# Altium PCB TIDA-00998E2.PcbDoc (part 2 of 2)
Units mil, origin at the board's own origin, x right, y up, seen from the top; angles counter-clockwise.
Board outline 2559.06 x 2559.06 mil, 2 copper layers (Top Layer, Bottom Layer), stack 62 mil thick; 110 components, 76 nets, 294 pads, 121 vias.
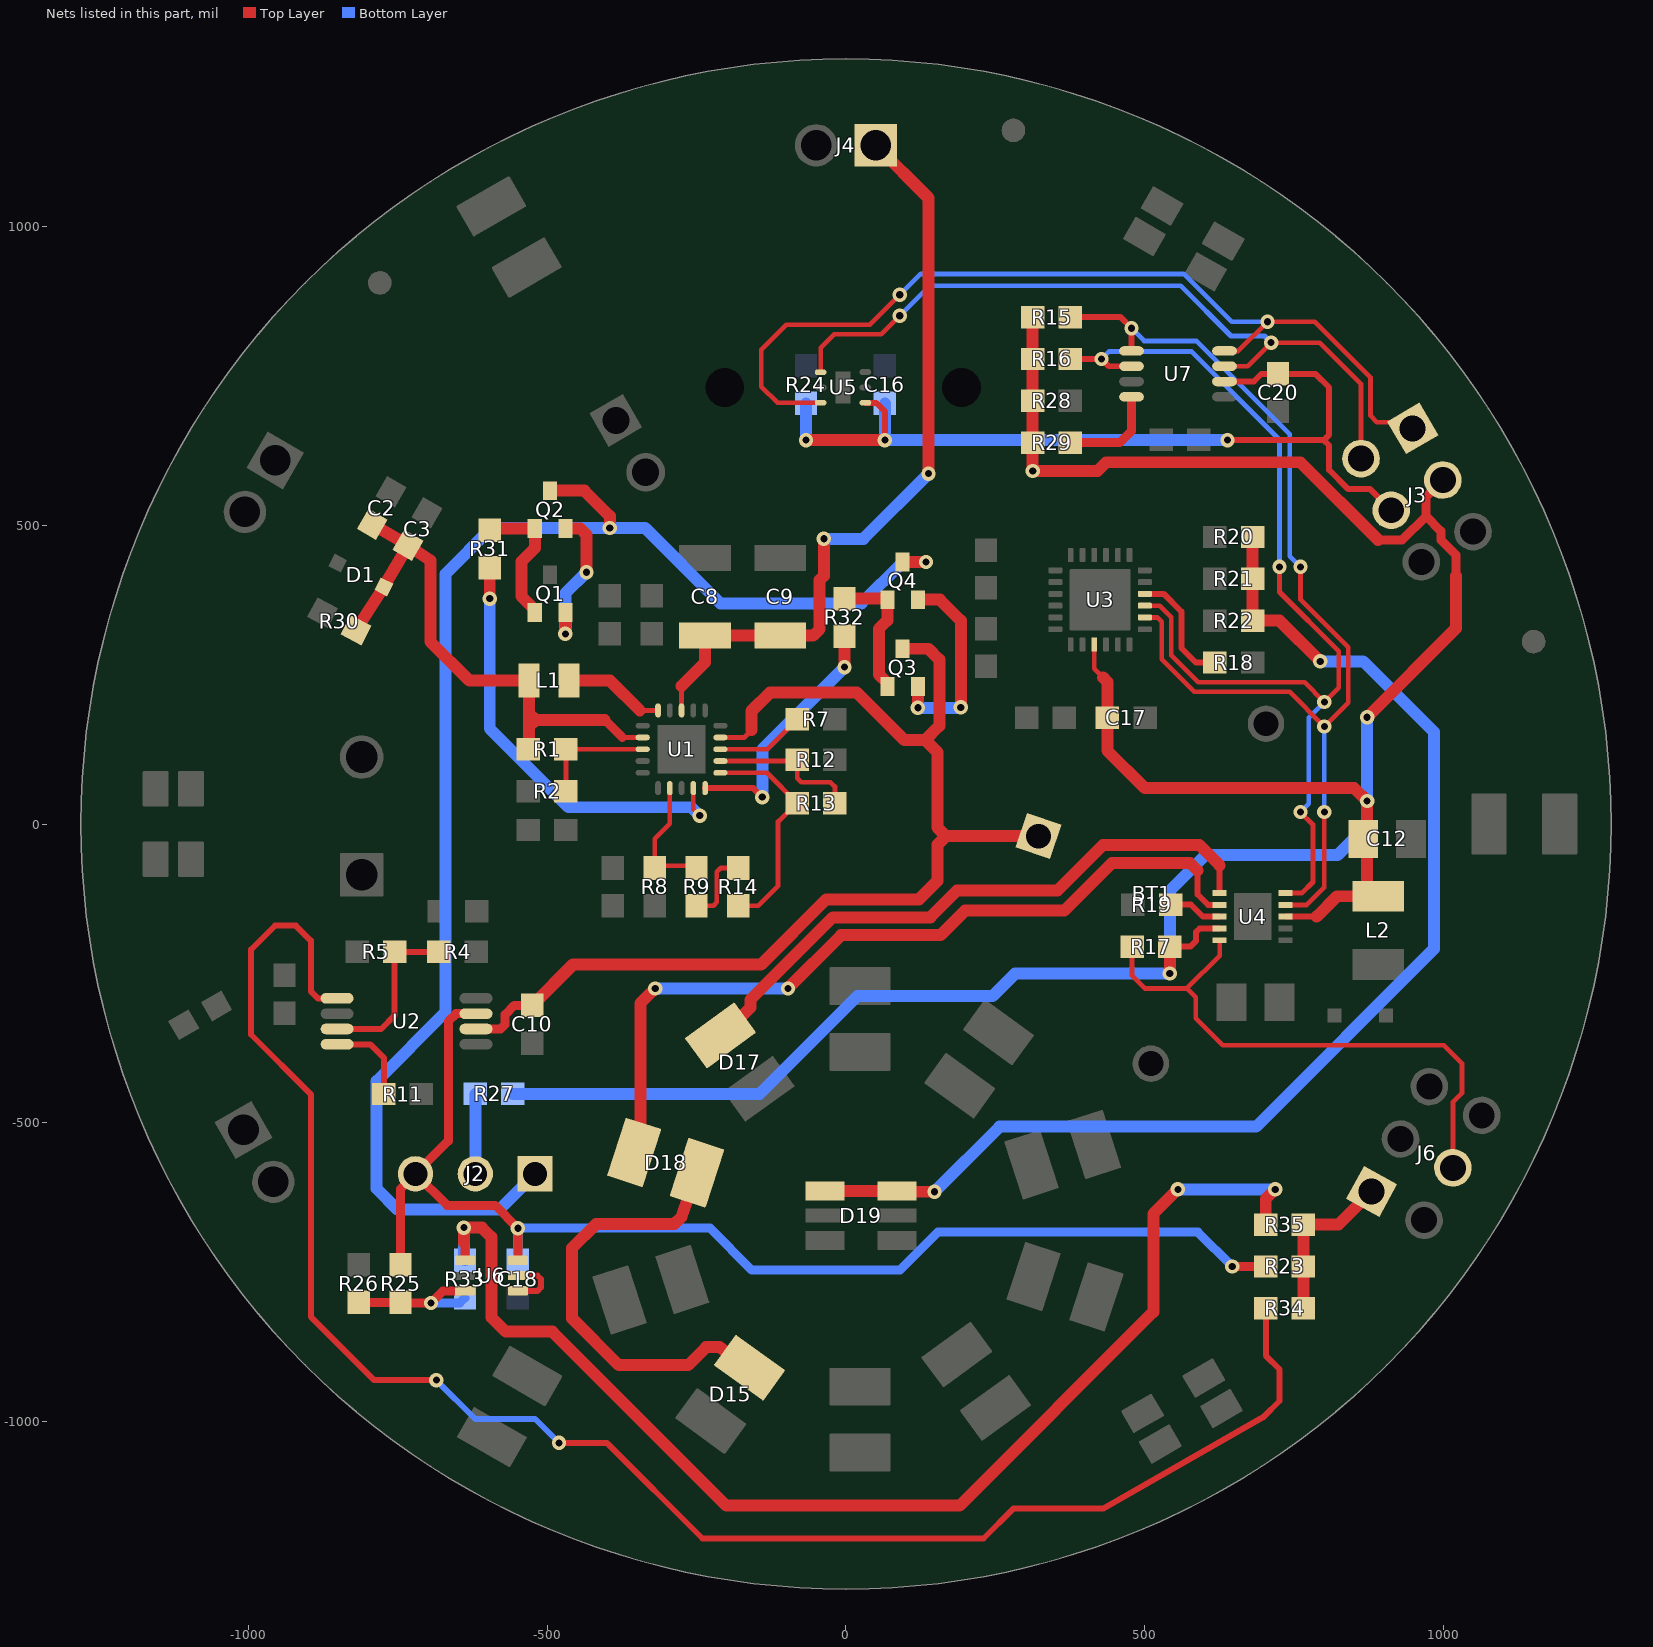
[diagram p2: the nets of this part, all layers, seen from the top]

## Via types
v1: diameter 24, hole 12, Top Layer to Bottom Layer, tented both sides, 107 vias
v2: diameter 19.68, hole 7.87, Top Layer to Bottom Layer, 10 vias
v3: diameter 19.68, hole 7.87, Top Layer to Bottom Layer, tented top, 4 vias

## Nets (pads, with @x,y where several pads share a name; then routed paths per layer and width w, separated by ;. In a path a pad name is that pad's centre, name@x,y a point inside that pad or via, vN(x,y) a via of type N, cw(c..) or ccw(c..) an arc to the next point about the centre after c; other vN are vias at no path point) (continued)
NetD15_2: D15.2 D18.1 | length 752.8
  Top Layer w20: D18.1@-249.35,-583.25 -275,-657 -287,-669 -418,-669 -458,-709 -458,-827 -380,-905 -264,-905 -234,-875 -211.29,-875 -207.87,-877.35 D15.2@-161.43,-909.33 D15.2@-161.26,-909.45
NetD17_2: D17.2 U4.1 | length 1037.2
  Top Layer w10: U4.1@624.88,-115.63 624.88,-69.12
  Top Layer w20: D17.2@-214.71,-347.22 -200.22,-347.22 -160,-307 -160,-294 -22,-156 141,-156 186,-111 354,-111 430,-35 590.76,-35 624.88,-69.12
NetD18_2: D18.2 U4.2 | length 1372.9
  Top Layer w10: 588,-78 588,-118 605.32,-135.32 U4.2@624.88,-135.32
  Top Layer w20: D18.2@-361.68,-546.75 -344,-529.07 -344,-300 v1(-319,-275) ; v1(-97,-275) -8,-186 158,-186 199,-145 365,-145 445,-65 575,-65 588,-78
  Bottom Layer w20: v1(-319,-275) v1(-97,-275)
NetD19_3: D19.3 D19.4 R20.2 R21.2 R22.2 | length 2069.8
  Top Layer w20: D19.3@-35.04,-613.66 D19.4@85.04,-613.66 86.38,-615 v1(148,-615) ; R20.2@680,480 R21.2@680,410 R22.2@680,340 725,340 v1(793,272)
  Bottom Layer w20: v1(148,-615) 257,-506 686,-506 983,-209 983,154 865,272 v1(793,272)
NetJ2_2: J2.2 R27.2 | length 133.7
  Bottom Layer w20: J2.2@-620,-585 R27.2@-620,-451.31
NetJ6_1: J6.1 R23.1 R34.2 R35.2 | length 278.7
  Top Layer w20: R34.2@765,-810 R35.2@765,-670 823.51,-670 J6.1@879.16,-614.35 J6.1@879.16,-615.84
NetL1_2: L1.2 U1.20 | length 169.7
  Top Layer w8: -344.96,189.96 U1.20@-314.37,189.96
  Top Layer w20: L1.2@-463.33,240 -395,240 -344.96,189.96
NetQ1_1: Q1.1 Q2.1 R31.2 | length 235.7
  Top Layer w20: R31.2@-595.78,491.5 -592.84,494.43 Q2.1@-520.47,494.43 -520.47,461.27 -542.88,438.86 -542.88,380.97 -520.47,358.56 Q1.1@-520.47,353.78
NetQ1_2: Q1.2 Q2.2 | length 256
  Top Layer w20: v1(-469.29,318) Q1.2@-469.29,353.78 ; Q2.2@-469.29,494.43 -444.43,494.43 -433.99,483.99 v1(-433.99,421)
  Bottom Layer w20: v1(-469.29,318) -469.29,385.7 v1(-433.99,421)
NetQ3_1: Q3.1 Q4.1 R32.2 | length 229.1
  Top Layer w20: R32.2@-2.59,376.91 67.27,376.91 Q4.1@69.09,375.08 69.09,340.57 55,326.48 55,250 69.09,235.91 Q3.1@69.09,230.08
NetQ3_2: Q3.2 Q4.2 | length 339
  Top Layer w20: v1(120.28,194.3) Q3.2@120.28,230.08 ; Q4.2@120.28,375.08 156.92,375.08 192,340 v1(192,195)
  Bottom Layer w20: v1(120.28,194.3) 191.3,194.3 v1(192,195)
NetR1_2: R1.2 R2.1 U1.3 | length 198.5
  Top Layer w8: R2.1@-468.5,55 R1.2@-468.5,125 U1.3@-339.96,125
NetR4_1: R4.1 R5.2 U2.3 | length 285.7
  Top Layer w10: U2.3@-851.14,-342.8 -777.5,-342.8 -754.7,-320 R5.2@-754.7,-213.74 R4.1@-681.2,-213.74
NetR7_2: R7.2 U1.13 | length 149.3
  Top Layer w8: U1.13@-210.04,125 -131.5,125 R7.2@-81.5,175
NetR8_2: R8.2 R9.1 U1.7 | length 215.6
  Top Layer w8: R8.2@-320,-73.58 R8.2@-320,-70 ; U1.7@-294.69,60.04 -294.69,0.31 -320,-25 R8.2@-320,-70 ; R9.1@-250,-73.58 -253.58,-70 R8.2@-320,-70
NetR9_2: R9.2 R14.2 | length 126
  Top Layer w8: R9.2@-250,-136.57 -221.57,-136.57 -216,-131 -216,-80 -209.58,-73.58 R14.2@-180,-73.58
NetR11_2: R11.2 U2.4 | length 148
  Top Layer w10: U2.4@-851.14,-368.39 -795.67,-368.39 -772.99,-391.06 R11.2@-772.99,-451.56
NetR12_2: R12.2 R13.1 U1.12 | length 256.4
  Top Layer w8: U1.12@-210.04,105.32 -83.42,105.32 R12.2@-81.5,107.24 -81.5,76.5 -75,70 -26,70 -18.5,62.5 R13.1@-18.5,35
NetR13_2: R13.2 R14.1 U1.11 | length 382.2
  Top Layer w8: U1.11@-210.04,85.63 -132.13,85.63 R13.2@-81.5,35 -82.72,35 -113.66,4.05 -113.66,-103.66 -146.57,-136.57 R14.1@-180,-136.57
NetR18_2: R18.2 U3.10 | length 200.5
  Top Layer w10: U3.10@499.8,384.84 531.16,384.84 561,355 561,294 585,270 R18.2@617.01,270
NetR19_2: R19.2 U4.3 | length 90.4
  Top Layer w10: R19.2@542.76,-135 577,-135 597,-155 U4.3@624.88,-155
NetR25_1: R25.1 R26.2 R33.1 U6.3 | length 247.4
  Top Layer w15: R26.2@-815,-801.5 -813.5,-800 R25.1@-745,-800 -744,-801 v1(-694,-801) -673.69,-780.69 U6.3@-637.27,-780.69
  Bottom Layer w15: v1(-694,-801) -645.77,-801 R33.1@-637.27,-792.5
NetR29_1: R29.1 U7.8 | length 167.3
  Top Layer w15: R29.1@375.26,637.75 457.75,637.75 477.5,657.5 U7.8@477.5,714.37
NetU6_4: U6.4 U6.5 | length 96.2
  Top Layer w10: U6.4@-548.68,-780.69 -515.69,-780.69 -510,-775 -510,-761 -515.91,-755.09 U6.5@-548.68,-755.09
RESET_LM: J6.4 R17.1 U4.5 | length 965.8
  Top Layer w8: R17.1@478.5,-205 478.5,-253.5 500,-275 570,-275 ; U4.5@624.88,-194.37 624.88,-220.12 570,-275 ; J6.4@1015,-575 1015,-465 1030,-450 1030,-400 1000,-370 630,-370 585,-325 585,-290 570,-275
SCL: R16.1 U3.9 U4.10 U7.6 | length 1745.3
  Top Layer w8: U3.9@499.8,365.16 524.84,365.16 544,346 544,282 589,237 767,237 v1(800,204) 824,228 824,289 725,388 v1(725,430) ; U4.10@735.12,-115.63 762.37,-115.63 781,-97 781,-1 v1(760,20)
  Top Layer w10: R16.1@375.26,777.75 v1(427.25,777.75) 439.45,765.55 U7.6@477.5,765.55
  Bottom Layer w8: v1(427.25,777.75) 439.49,790 578,790 725,643 v1(725,430) ; v1(760,20) 774,34 774,178 v1(800,204)
SCL1: J3.2 U5.4 U7.3 | length 1274.6
  Top Layer w8: U5.4@-42.4,755.59 -42.4,796.6 -20,819 59,819 v1(90,850) ; U7.3@633.02,765.55 671.55,765.55 v1(711,805) 792,805 861.37,735.63 J3.2@861.37,611.1
  Bottom Layer w8: v1(90,850) 140,900 560,900 643.87,816.13 699.87,816.13 v1(711,805)
SDA: R15.1 U3.8 U4.9 U7.5 | length 1790.6
  Top Layer w8: U3.8@499.8,345.47 520.53,345.47 528,338 528,275.37 582.37,221 742,221 v1(800,163) 840,203 840,295.63 760,375.63 v1(760,430) ; U4.9@735.12,-135.32 770.68,-135.32 800,-106 v1(800,20)
  Top Layer w10: R15.1@375.26,847.75 459.25,847.75 477.5,829.5 v1(477.5,829) U7.5@477.5,791.14
  Bottom Layer w8: v1(477.5,829) 498.5,808 586,808 742,652 742,448 v1(760,430) ; v1(800,20) v1(800,163)
SDA1: J3.1 U5.6 U7.4 | length 1550.7
  Top Layer w8: U5.6@-42.4,704.41 -114.41,704.41 -141.56,731.56 -141.56,793.44 -100,835 40,835 v1(90,885) ; U7.4@633.02,791.14 656.14,791.14 v1(705,840) 784,840 877.37,746.63 877.37,682.63 888,672 937.26,672 J3.1@947.7,661.56
  Bottom Layer w8: v1(90,885) 125,920 565,920 645,840 v1(705,840)
STAT_PMUX: R34.1 U2.1 | length 2926.7
  Top Layer w10: U2.1@-851.14,-291.61 -883.39,-291.61 -895,-280 -895,-195 -920,-170 -955,-170 -995,-210 -995,-352 -895,-452 -895,-824 -789,-930 v1(-685,-930) ; v1(-480,-1035) -400,-1035 -240,-1195 230,-1195 280,-1145 430,-1145 698.63,-991.36 725,-964.99 725,-912 702.01,-889.01 R34.1@702.01,-810
  Bottom Layer w10: v1(-685,-930) -620,-995 -520,-995 v1(-480,-1035)
VBAT_PRI: BT1.1 C10.1 Q3.3 U1.14 U2.6 | length 1933
  Top Layer w8: U1.14@-210.04,144.69 -170.31,144.69 -158,157
  Top Layer w15: U2.6@-618.86,-342.8 -577.8,-342.8 -570,-335 -570,-318.8 -554.7,-303.5 C10.1@-525,-303.5
  Top Layer w20: C10.1@-525,-303.5 -456.5,-235 -142,-235 -33,-126 122,-126 153,-95 153,-34.64 167.32,-20.32 ; -158,157 -158,189 -127,220 18,220 97.5,140.5 132.5,140.5 ; Q3.3@94.68,293.07 137.93,293.07 156,275 156,164 132.5,140.5 ; BT1.1@322.04,-20.32 167.32,-20.32 ; 132.5,140.5 153,120 153,-6 167.32,-20.32
VBAT_SEC: C8.1 C9.1 J4.1 U1.18 | length 1295.9
  Top Layer w8: U1.18@-275,189.96 -275,231
  Top Layer w20: -275,231 -235.63,270.37 -235.63,313.07 -233.66,315.04 C9.1@-110,315.04 -54.96,315.04 -44,326 -44,408 -37,415 v1(-37,477) ; J4.1@50,1135 138,1047 v1(138,586)
  Bottom Layer w20: v1(-37,477) 29,477 v1(138,586)
VGS_PRI: R32.1 U1.10 | length 427.7
  Top Layer w10: U1.10@-235.63,60.04 -155.04,60.04 v1(-140,45)
  Top Layer w20: v1(-2.59,262.32) R32.1@-2.59,313.91
  Bottom Layer w20: v1(-140,45) -140,124.91 v1(-2.59,262.32)
VGS_SEC: R31.1 U1.9 | length 731
  Top Layer w8: U1.9@-255.32,60.04 -255.32,24.83 v1(-244.49,14)
  Top Layer w20: v1(-595.78,376.91) R31.1@-595.78,428.5
  Bottom Layer w20: v1(-595.78,376.91) -595.78,159.58 -464.2,28 -258.49,28 v1(-244.49,14)
VIN_BQ: C2.1 C3.1 D1.1 L1.1 R1.1 R30.2 U1.2 | length 946.2
  Top Layer w8: -374.17,144.69 U1.2@-339.96,144.69
  Top Layer w15: -403.49,174 -374.17,144.69
  Top Layer w20: R30.2@-819.4,324.34 D1.1@-772.9,396.6 C3.1@-732.3,466.04 ; C2.1@-792.3,501.04 C3.1@-732.3,466.04 ; R1.1@-531.5,125 -530.25,126.24 -530.25,163 ; -403.49,174 -519.25,174 ; C3.1@-732.3,466.04 -695,440.34 -695,305 -630,240 L1.1@-530.25,240 -530.25,185 ; -530.25,163 -519.25,174 ; -530.25,163 -530.25,185 ; -530.25,185 -519.25,174
VIN_DRIVER: C12.2 C17.1 J3.3 L2.1 R15.2 R16.2 R17.2 R27.1 R28.2 R29.2 U3.3 U4.4 U4.8 | length 4500.4
  Top Layer w8: U3.3@415.16,300.2 415.16,259.84 430,245
  Top Layer w10: R17.2@541.5,-205 576,-205 585,-196 585,-181 591.31,-174.69 U4.4@624.88,-174.69 ; U4.8@735.12,-155 787,-155
  Top Layer w15: 890,475 930,475 970,515 ; J3.3@998.16,575.23 970,547.07 970,515 ; 1020,415 1020,450 995,475 995,490 970,515
  Top Layer w20: R15.2@312.27,847.75 R16.2@312.27,777.75 R28.2@312.27,707.75 R29.2@312.27,637.75 v1(312.27,590.25) 420.25,590.25 435,605 760,605 890,475 ; 430,245 437.18,237.82 C17.1@437.18,177.73 437.18,122.82 500,60 850,60 v1(871.54,38.46) 871.54,-102.36 L2.1@890,-120.83 821.17,-120.83 787,-155 ; v1(541.5,-250) R17.2@541.5,-205 ; v1(871.54,178.46) 1020,326.93 1020,415
  Bottom Layer w20: R27.1@-557.01,-451.31 -144.31,-451.31 19,-288 245,-288 283,-250 v1(541.5,-250) 541.5,-111.5 600.99,-52 822,-52 871.54,-2.46 v1(871.54,38.46) v1(871.54,178.46)
VOUT_BQ: J2.1 Q2.3 Q4.3 | length 2472.9
  Top Layer w20: Q2.3@-494.88,557.43 -437.43,557.43 -395,515 v1(-395,495) ; Q4.3@94.68,438.07 v1(133.7,438.07)
  Bottom Layer w20: J2.1@-520,-585 -580,-645 -750,-645 -785,-610 -785,-430 -670,-315 -670,418 -593,495 v1(-395,495) -336,495 -210,369 25.61,369 94.68,438.07 v1(133.7,438.07)
VOUT_PMUX: C18.1 J2.3 R23.2 R25.2 U2.7 U6.6 | length 2137.5
  Top Layer w15: R25.2@-745,-737.01 -745,-610 J2.3@-720,-585 ; U2.7@-618.86,-317.2 -652.2,-317.2 -665,-330 -665,-530 J2.3@-720,-585 ; U6.6@-548.68,-729.5 v1(-548.68,-676) -586.68,-638 -667,-638 J2.3@-720,-585 ; v1(646,-740) R23.2@702.01,-740
  Bottom Layer w15: C18.1@-548.68,-729.5 v1(-548.68,-676) -227.37,-676 -157.37,-746 90,-746 153.63,-682.37 588.37,-682.37 v1(646,-740)
VPMUX_LOW: R33.2 R35.1 U6.1 | length 2128.6
  Top Layer w15: U6.1@-646.5,-729.5 U6.1@-637.27,-729.5 -637.27,-702.73 -639,-701
  Top Layer w20: -639,-701 v1(-639,-675) -609,-675 -593,-691 -593,-825 -569,-849 -491,-849 -200,-1140 190,-1140 514,-816 514,-652 v1(555,-611) ; R35.1@702.01,-670 702.01,-626.99 v1(718,-611)
  Bottom Layer w20: v1(-639,-675) -639,-727.77 R33.2@-637.27,-729.5 ; v1(555,-611) v1(718,-611)
VREF1: C16.1 C20.1 J3.4 R24.2 U5.1 U7.2 | length 1542.6
  Top Layer w10: U5.1@32.4,704.41 50.59,704.41 65,690 v1(65,642) ; U7.2@633.02,739.96 681.96,739.96 694.95,752.95 C20.1@722.5,752.95 785.05,752.95 808,730 808,651 799,642 ; v1(638,642) 799,642 ; J3.4@911.84,524.77 876.6,560 840,560 808,592 808,633 799,642
  Top Layer w20: v1(-67,642) v1(65,642)
  Bottom Layer w20: v1(-67,642) R24.2@-67,703.5 ; C16.1@65,703.5 v1(65,642) v1(638,642)
pads on no net: D19.1 D19.5 D19.6 FID1.1 FID2.1 FID3.1 FID4.1 FID5.1 FID6.1 U1.8 U3.7

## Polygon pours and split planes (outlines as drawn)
NetD1_2 on Top Layer "NETD1_2_L01_P002" (solid, remove dead copper, pour order 2): -1045,424.21 -1045,331.48 -1038.52,325 -871.48,325 -845,375 -845,415 -830,445 -860,460 -955,460 -965,470 -965,535 -990,560 -1023.27,560 -1045,538.27
GND on Bottom Layer "GND_L02_P004" (solid, remove dead copper, pour order 4): 15,1250 -70,1250 -220,1235 -450,1170 -685,1050 -845,925 -1015,735 -1125,550 -1185,410 -1230,245 -1250,45 -1250,-90 -1235,-220 -1200,-360 -1155,-485 -1080,-635 -985,-775 -895,-880 -750,-1005 -580,-1110 -410,-1185 -245,-1230 -95,-1250 35,-1250 185,-1240 345,-1205 565,-1120 800,-965 940,-825 1090,-620 1190,-390 1240,-185 1250,-10 1245,150 1210,320 1160,480 1080,635 975,785 895,875 795,970 670,1060 575,1115 490,1155 365,1200 220,1235 110,1250 15,1250

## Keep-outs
Keep-Out Layer:
  circle w10: c0,0 r1259.84

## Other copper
Top Layer:
  text ".Layer_Name" at -1723,-2858.49 h60
Bottom Layer:
  text ".Layer_Name" at -1723,-2858.49 h60

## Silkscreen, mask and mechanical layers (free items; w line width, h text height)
Top Overlay:
  lines w10: 280,1045 280,895 ; 280,895 272,903 288,903 280,895
  text ".PCB_Rev" at -393,746 h60
  text ".PRJ_Number" at -928,741 h108.27
  text "GND" at 663,94 h30
  text "+" at 374,-50 h40
  text "GND" at 471,-352 h30
  text ".Layer_Name" at -1723,-2858.49 h60
Bottom Overlay:
  circle w10: c45,-642 r12.81
  text "GND" at 743,94 h30
  text "+" at 374,-50 h40
  text "GND" at 551,-352 h30
  text ".Layer_Name" at -1723,-2858.49 h60
Top Paste:
  text ".Layer_Name" at -1723,-2858.49 h60
Bottom Paste:
  text ".Layer_Name" at -1723,-2858.49 h60
Top Solder:
  text ".Layer_Name" at -1723,-2858.49 h60
  text ".Layer_Name" at -1723,-2858.49 h60
Bottom Solder:
  text ".Layer_Name" at -1723,-2858.49 h60
Drill Guide:
  text ".Layer_Name" at -1723,-2858.49 h60
M1 Board Outline:
  circle w10: c0,0 r1279.53
  text "M1 Board Outline" at -1723,-2858.49 h60
M2 Board Dimensions:
  rectangle: -2300,-2275 -2175,-2150
  rectangle: -2175,-2400 -1800,-2275
  lines w7: -2300,-2275 -1300,-2275 ; -2175,-2400 -2175,-2150 ; -2050,-2400 -2050,-2150 ; -1800,-2400 -1800,-2150 ; -1550,-2400 -1550,-2150 ; -2300,-2400 -1300,-2400 -1300,-2150 -2300,-2150 -2300,-2400
M3 3D STEP Top:
  text ".Layer_Name" at -1723,-2858.49 h60
M4 3D STEP Bottom:
  text ".Layer_Name" at -1723,-2858.49 h60
M5 Assembly Top:
  circle w10: c50,1135 r5.66
  circle w10: c-1007.64,-511.64 r7.95
  circle w10: c-954.63,608.09 r6.88
  circle w10: c586,-91 r5.83
  circle w10: c-521,466 r6.08
  circle w10: c-520,324 r6.08
  circle w10: c70,342 r6.08
  circle w10: c68,196 r6.08
  lines w6: 607.17,-221.93 607.17,-88.07 752.83,-88.07 752.83,-221.93 607.17,-221.93
  lines w10: -2592,-2930.17 4008,-2930.17 ; -2592,-2726.83 4010,-2726.83 ; -2592,-2523.5 -2592,-3133.5 1413,-3133.5 4010,-3133.5 4010,-2523.5 -2591.5,-2523.5 -2591.5,-3133.5 -1016,-3133.5 ; -127,-3133.5 -127,-2523.5 ; 1140,-2726.83 1140,-2523.5 ; 1980,-2726.83 1980,-2523.5 ; 2602,-3140 2602,-2937.17
  text "COMPONENTS MARKED 'DNP' SHOULD NOT BE POPULATED." at -1146.5,-2318.5 h60
  text "ASSEMBLY VARIANT:" at -1147,-2434 h60
  text ".VariantName" at -111,-2434 h60
  text "PCB VIEWED FROM TOP SIDE" at -2528.5,-2655.67 h60
  text "BOARD #:" at -52,-2655.67 h60
  text ".PRJ_Number" at 493.5,-2655.67 h60
  text "REV:" at 1338,-2655.67 h60
  text ".PCB_Rev" at 1629.5,-2655.67 h60
  text "SVN REV:" at 2176,-2655.67 h60
  text ".VersionControl_RevNumber" at 2682,-2655.67 h60
  text ".Layer_Name" at -1723,-2858.49 h60
  text "TID #:" at -52,-2859 h60
  text ".TID" at 493.5,-2859 h60
  text "LAYER NAME =" at -2525.5,-2862.34 h60
  text "PLOT NAME =" at -2528.5,-3064.34 h60
  text ".plot_File_Name" at -1723,-3064.34 h60
  text "GENERATED    :" at -50,-3064.34 h60
  text ".Print_Date" at 819.5,-3064.34 h60
  text ".Print_Time" at 1548.5,-3064.34 h60
  text "TEXAS INSTRUMENTS" at 2813,-3064.34 h60
M6 Assembly Bottom:
  circle w10: c-385,674.91 r6.67
  circle w10: c322.04,-20.32 r10.63
  lines w6: 250,-20 280,-20 ; 265,-35 265,-5
  lines w10: -2592.5,-2727.33 4009.5,-2727.33 ; -2590.5,-2930.67 4009.5,-2930.67 ; -1184.5,-3140.5 -1184.5,-2937.67 ; -562.5,-2727.33 -562.5,-2524 ; 277.5,-2727.33 277.5,-2524 ; 1544.5,-3134 1544.5,-2524 ; 2433.5,-3134 4009,-3134 4009,-2524 -2592.5,-2524 -2592.5,-3134 4.5,-3134 4009.5,-3134 4009.5,-2524
  text "COMPONENTS MARKED 'DNP' SHOULD NOT BE POPULATED." at 3802,-2318 h60
  text ".VariantName" at 2758,-2434 h60
  text "ASSEMBLY VARIANT:" at 3797,-2434 h60
  text ".VersionControl_RevNumber" at -1264.5,-2656.17 h60
  text "SVN REV:" at -758.5,-2656.17 h60
  text ".PCB_Rev" at -212,-2656.17 h60
  text "REV:" at 79.5,-2656.17 h60
  text ".PRJ_Number" at 924,-2656.17 h60
  text "BOARD #:" at 1469.5,-2656.17 h60
  text "PCB VIEWED FROM BOTTOM SIDE" at 3946,-2656.17 h60
  text ".Layer_Name" at 3132,-2852 h60
  text "LAYER NAME =" at 3939,-2855.84 h60
  text ".TID" at 924,-2859.5 h60
  text "TID #:" at 1469.5,-2859.5 h60
  text "TEXAS INSTRUMENTS" at -1395.5,-3064.84 h60
  text ".Print_Time" at -131,-3064.84 h60
  text ".Print_Date" at 598,-3064.84 h60
  text "GENERATED    :" at 1467.5,-3064.84 h60
  text ".plot_File_Name" at 3140.5,-3064.84 h60
  text "PLOT NAME =" at 3946,-3064.84 h60
M9 Title Sheet:
  drawing of 57 lines, arcs and shapes, not listed
  text "1" at -1560.16,6036.5 h70
  text "2" at 935.5,6036.5 h70
  text "3" at 3424.84,6036.5 h70
  text "4" at 5931.51,6036.5 h70
  text "5" at 8430.5,6036.5 h70
  text "6" at 10935.5,6036.5 h70
  text "A" at -2716.5,4893.5 h70
  text "A" at 12083.5,4893.5 h70
  text "B" at -2716.5,2513.5 h70
  text "B" at 12083.5,2513.5 h70
  text "C" at -2716.5,138.5 h70
  text "C" at 12083.5,138.5 h70
  text "PROJECT TITLE:" at 9043.5,-1722.5 h45
  text ".PRJ_Title" at 9093.5,-1855.83 h70
  text "DESIGNED FOR:" at 9043.5,-2023.5 h45
  text ".PRJ_Customer" at 9093.5,-2163.5 h70
  text "D" at -2716.5,-2231.5 h70
  text "D" at 12083.5,-2231.5 h70
  text "FILE NAME:" at 9043.5,-2323.5 h45
  text ".PCB_File_Name_No_Path" at 9093.5,-2443.5 h70
  text "Texas Instruments (TI) and/or its licensors do not warrant the accuracy or completeness of this specification" at 4074,-2605.34 h45
  text "ENGINEER:" at 9043.5,-2613.5 h45
  text "LAYOUT BY:" at 10548.5,-2613.5 h45
  text "or any information contained therein. TI and/or its licensors do not warrant that this design will meet" at 4029.01,-2718 h45
  text ".PRJ_Engineer" at 9093.5,-2768.49 h70
  text ".PCB_Layout" at 10599,-2768.49 h70
  text "the specifications, will be suitable for your application or fit for any particular purpose, or will operate in" at 4029.01,-2830.67 h45
  text "ALTIUM DESIGNER VERSION:" at 10548.5,-2923.5 h45
  text "an implementation. TI and/or its licensors do not warrant that the design is production worthy. You should" at 4029.01,-2943.33 h45
  text "completely validate and test your design implementation to confirm the system functionality for your application." at 4074,-3056 h45
  text ".print_Scale" at 9093.5,-3056.83 h70
  text ".Application_BuildNumber" at 10599,-3056.83 h70
  text "1" at -1560.16,-3263.5 h70
  text "2" at 935.5,-3263.5 h70
  text "3" at 3424.84,-3263.5 h70
  text "4" at 5931.51,-3263.5 h70
  text "5" at 8430.5,-3263.5 h70
  text "6" at 10935.5,-3263.5 h70
M10 Fab Notes:
  drawing of 189 lines, arcs and shapes, not listed
  text "DESIGN INFORMATION" at 10078.02,4201 h60
  text "MIN. TRACK WIDTH:" at 9433.46,4021 h60
  text "8" at 10529.7,4021 h60
  text "MIL" at 10708,4021 h60
  text "MIL" at 10709,3903 h60
  text "7.874" at 10410,3894 h60
  text "MIN. CLEARANCE:" at 9433.46,3889 h60
  text "MIL" at 10713,3763 h60
  text "19.69" at 10418,3759 h60
  text "MIN. VIA PAD SIZE:" at 9433.46,3757 h60
  text "EXTERNAL" at 11072,3616 h60
  text "0.15mm (5.9055 MIL)" at 10128.46,3615.29 h60
  text "MINIMUM ANNULAR RING" at 9104.23,3611 h60
  text "PER" at 9304.23,3493 h60
  text "IPC-D-275 CLASS 2 LEVEL C" at 9524.23,3493 h60
  text "MIL, HOLES" at 11012.46,3380.71 h60
  text "+/-" at 10620,3380 h60
  text "+/-" at 11474,3380 h60
  text "REGISTRATION TOLERANCES:" at 9104.23,3375 h60
  text "METAL" at 10304,3375 h60
  text "5" at 10880.2,3375 h60
  text "3" at 11713.2,3375 h60
  text "MIL" at 11829.46,3375 h60
  text "+/-" at 11474,3262 h60
  text "HOLE SIZE TOLERANCE (UNLESS OTHERWISE SPECIFIED):" at 9104.23,3257 h60
  text "3" at 11713.2,3257 h60
  text "MIL" at 11829.46,3257 h60
  text "MATERIAL:" at 9029.46,3047.54 h60
  text "FR-4 High Tg" at 10015.9,2907.21 h60
  text "FR-408" at 9450.46,2898.64 h60
  text "OTHER" at 10938.46,2898.64 h60
  text "X" at 9861,2895 h60
  text "63 MIL (1.6mm) +/-10%" at 9770.56,2735.92 h60
  text "THICKNESS:" at 9104.23,2731.64 h60
  text "X" at 9642.4,2731.64 h60
  text "OTHER" at 11055.46,2731.64 h60
  text "TOLERANCE:" at 9104.23,2573.64 h60
  text "X" at 9943.53,2573.64 h60
  text "ANSI IPC-6012 TYPE 3 CLASS 2" at 10130.48,2573.64 h60
  text "OTHER +/-" at 10130.46,2417.64 h60
  text "BOW & TWIST:" at 9104.23,2260.64 h60
  text "X" at 9943.53,2260.64 h60
  text "ANSI IPC-6012 TYPE 3 CLASS 2" at 10130.48,2260.64 h60
  text "OTHER +/-" at 10130.46,2102.13 h60
  text "DRILLING:" at 9029.46,1963.64 h60
  text "REFERENCE:" at 9104.23,1846.64 h60
  text "X" at 9752.46,1846.64 h60
  text "AS SHOWN" at 9939.46,1846.64 h60
  text "X" at 10653.46,1846.64 h60
  text "NC_DRILL FILES" at 10790.46,1846.64 h60
  text "PTH COPPER THICKNESS:" at 9104.23,1688.64 h60
  text "X" at 10234.46,1688.64 h60
  text "20-30 um" at 10371.46,1688.64 h60
  text "OTHER" at 11088.46,1688.64 h60
  text "BOARD FINISH:" at 9029.46,1529.64 h60
  text "SILKSCREEN:" at 9184.68,1411.64 h60
  text "X" at 10133.46,1411.64 h60
  text "TOP" at 10259.46,1411.64 h60
  text "X" at 10643.46,1411.64 h60
  text "BOTTOM" at 10770.46,1411.64 h60
  text "SILKSCREEN COLOR:" at 9184.68,1244.64 h60
  text "X" at 10132.42,1244.64 h60
  text "WHITE" at 10259.46,1244.64 h60
  text "OTHER" at 10770.46,1244.64 h60
  text "X" at 10263.42,1085.44 h60
  text "GREEN" at 10390.46,1085.44 h60
  text "OTHER" at 11008.46,1085.44 h60
  text "SOLDER RESIST COLOR:" at 9184.68,1074.64 h60
  text "X" at 10263.42,915.44 h60
  text "MATTE" at 10390.46,915.44 h60
  text "SEMI-GLOSS" at 11008,914.8 h60
  text "IMMERSION GOLD (ENIG)" at 10090.46,726.92 h60
  text "ENEPIG" at 11428,723.64 h60
  text "SURFACE FINISH:" at 9029.46,722.64 h60
  text "X" at 9903.51,722.64 h60
  text "IMM. TIN/SILVER OR EQUIV" at 9359,565.64 h60
  text "OTHER" at 10790.46,565.64 h60
  text "ARRAY/PANEL:" at 9029.46,386.64 h60
  text "CUT AND TRIM PER M1 BOARD OUTLINE" at 10090.46,382.35 h60
  text "N.C. ROUTE" at 10090.46,230.64 h60
  text "X" at 10769.46,230.64 h60
  text "V. SCORE" at 10956.46,230.64 h60
  text "CERTIFICATION:" at 9029.46,93.64 h60
  text "MATERIALS AND WORKMANSHIP FOR ALL PCBS" at 9754.46,93.64 h60
  text "TO MEET OR EXCEED THE REQUIREMENTS OF:" at 9754.46,-4.36 h60
  text "X" at 9380.96,-140.87 h60
  text "ANSI IPC-A-600F CLASS ->" at 9519.96,-140.87 h60
  text "X" at 11159.02,-140.87 h60
  text "2" at 11277.96,-140.86 h60
  text "1" at 10962.96,-142.36 h60
  text "3" at 11631.96,-142.36 h60
  text "X" at 10195.02,-300.36 h60
  text "RoHS" at 10331.96,-300.36 h60
  text "OTHER" at 10976.36,-300.36 h60
  text "PER ORDER" at 11373.42,-300.36 h60
  text "ALL BOARDS MUST MEET OR EXCEED UL94-V0 REQUIREMENTS." at 9057,-466 h60
  text "PCB MUST BEAR THE UL94V-0 UL REGISTERED MATERIAL ID NUMBER" at 9057,-586 h60
  text "VIA TENTING:" at 10188,-736 h60
  text "X" at 10948,-738 h60
  text "YES" at 10737.67,-745.08 h60
  text "NO" at 11102.47,-750.31 h60
  text "ADDITIONAL REQUIREMENTS:" at 9029.46,-759.36 h60
  text "IMPEDANCE CONTROL:" at 10210,-865 h60
  text "YES" at 11194,-866 h60
  text "X" at 11736,-873 h60
  text "MICROSECTION:" at 9104.23,-874.36 h60
  text "YES" at 10009.96,-874.36 h60
  text "NO" at 11569.47,-883.31 h60
  text "REQUIRED" at 10871.46,-1030.51 h60
  text "BARE BOARD ELEC. TEST:" at 9104.23,-1033.36 h60
  text "NONE" at 10409.96,-1033.36 h60
  text "X" at 10744.46,-1033.36 h60
  text "PER ORDER" at 11463.46,-1033.36 h60
M11 Gerber Information:
  lines w10: -2592,-2930.17 4008,-2930.17 ; -2592,-2726.83 4010,-2726.83 ; -2592,-2523.5 -2592,-3133.5 1413,-3133.5 4010,-3133.5 4010,-2523.5 -2591.5,-2523.5 -2591.5,-3133.5 -1016,-3133.5 ; -127,-3133.5 -127,-2523.5 ; 1140,-2726.83 1140,-2523.5 ; 1980,-2726.83 1980,-2523.5 ; 2602,-3140 2602,-2937.17
  text "ALL ARTWORK VIEWED FROM TOP SIDE" at -2528.5,-2655.67 h60
  text "BOARD #:" at -52,-2655.67 h60
  text ".PRJ_Number" at 493.5,-2655.67 h60
  text "REV:" at 1338,-2655.67 h60
  text ".PCB_Rev" at 1629.5,-2655.67 h60
  text "SVN REV:" at 2176,-2655.67 h60
  text ".VersionControl_RevNumber" at 2682,-2655.67 h60
  text "LAYER NAME =" at -2528.5,-2858.49 h60
  text "TID #:" at -52,-2859 h60
  text ".TID" at 493.5,-2859 h60
  text "PLOT NAME =" at -2528.5,-3064.34 h60
  text ".plot_File_Name" at -1723,-3064.34 h60
  text "GENERATED    :" at -50,-3064.34 h60
  text ".Print_Date" at 819.5,-3064.34 h60
  text ".Print_Time" at 1548.5,-3064.34 h60
  text "TEXAS INSTRUMENTS" at 2813,-3064.34 h60
M12 Stackup:
  drawing of 191 lines, arcs and shapes, not listed
  text "Layer" at 7525.34,5865 h60
  text "Name" at 7935.26,5865 h60
  text "Material" at 8865,5865 h60
  text "Thickness" at 9724.77,5865 h60
  text "Constant" at 10374.6,5865 h60
  text "Board Layer Stack" at 10944.46,5865 h60
  text "1" at 7525.34,5745 h60
  text "Top Overlay" at 7935.26,5745 h60
  text "2" at 7525.34,5625 h60
  text "Top Solder" at 7935.26,5625 h60
  text "Solder Resist" at 8865,5625 h60
  text "0.40mil" at 9724.77,5625 h60
  text "3.5" at 10374.6,5625 h60
  text "3" at 7525.34,5505 h60
  text "Top Layer" at 7935.26,5505 h60
  text "Copper" at 8865,5505 h60
  text "1.40mil" at 9724.77,5505 h60
  text "4" at 7525.34,5385 h60
  text "Dielectric1" at 7935.26,5385 h60
  text "FR-4 High Tg" at 8865,5385 h60
  text "59.20mil" at 9724.77,5385 h60
  text "4.8" at 10374.6,5385 h60
  text "5" at 7525.34,5265 h60
  text "Bottom Layer" at 7935.26,5265 h60
  text "Copper" at 8865,5265 h60
  text "1.40mil" at 9724.77,5265 h60
  text "6" at 7525.34,5145 h60
  text "Bottom Solder" at 7935.26,5145 h60
  text "Solder Resist" at 8865,5145 h60
  text "0.40mil" at 9724.77,5145 h60
  text "3.5" at 10374.6,5145 h60
  text "7" at 7525.34,5025 h60
  text "Bottom Overlay" at 7935.26,5025 h60
M13 Component Bodies Top:
  text ".Layer_Name" at -1723,-2858.49 h60
M14 Component Bodies Bottom:
  text ".Layer_Name" at -1723,-2858.49 h60
M15 Courtyards Top:
  text ".Layer_Name" at -1723,-2858.49 h60
M16 Courtyards Bottom:
  text ".Layer_Name" at -1723,-2858.49 h60
Drill Drawing:
  circle w10: c2520.31,-336.48 r27.67
  circle w10: c2520.31,-460.98 r16.6
  circle w10: c2520.31,-460.98 r27.67
  lines w10: 2492.64,-723.82 2506.47,-723.82 2520.31,-737.65 2534.14,-723.82 2547.97,-723.82 2534.14,-709.98 2547.97,-696.15 2534.14,-696.15 2520.31,-682.32 2506.47,-696.15 2492.64,-696.15 2506.47,-709.98 2492.64,-723.82 ; 2492.64,-599.32 2506.47,-599.32 2506.47,-613.15 2534.14,-613.15 2534.14,-599.32 2547.97,-599.32 2547.97,-571.65 2534.14,-571.65 2534.14,-557.82 2506.47,-557.82 2506.47,-571.65 2492.64,-571.65 2492.64,-599.32 ; 2492.64,-239.65 2547.97,-239.65 2547.97,-184.32 2492.64,-184.32 2492.64,-239.65 ; 2492.64,-115.15 2547.97,-115.15 2547.97,-59.82 2492.64,-59.82 2492.64,-115.15 ; 2492.64,23.18 2506.47,23.18 2520.31,9.35 2534.14,23.18 2547.97,23.18 2534.14,37.02 2547.97,50.85 2534.14,50.85 2520.31,64.68 2506.47,50.85 2492.64,50.85 2506.47,37.02 2492.64,23.18 ; 2492.64,189.18 2547.97,189.18 2520.31,133.85 2492.64,189.18 ; 2492.64,286.02 2520.31,258.35 2547.97,286.02 2520.31,313.68 2492.64,286.02 ; 2503.7,-718.28 2512.01,-718.28 2520.31,-726.58 2528.6,-718.28 2536.9,-718.28 2528.6,-709.98 2536.9,-701.68 2528.6,-701.68 2520.31,-693.38 2512.01,-701.68 2503.7,-701.68 2512.01,-709.98 2503.7,-718.28 ; 2503.7,-104.08 2536.9,-104.08 2536.9,-70.88 2503.7,-70.88 2503.7,-104.08
  lines w12: 2442.48,-775 5145.47,-775 ; 2442.48,345.5 5145.47,345.5 ; 2780.49,-899.5 2780.49,470 ; 3112.65,-899.5 3112.65,470 ; 3749.13,-899.5 3749.13,470 ; 4008.33,-899.5 4008.33,470 ; 4383.57,-899.5 4383.57,470 ; 2442.48,-899.5 5145.47,-899.5 5145.47,470 2442.48,470 2442.48,-899.5
  text "Symbol" at 2517.18,382.85 h72
  text "Quantity" at 2817.84,382.85 h72
  text "Finished Hole Size" at 3150,382.85 h72
  text "Plated" at 3786.48,382.85 h72
  text "Hole Type" at 4045.68,382.85 h72
  text "Drill Layer Pair" at 4420.92,382.85 h72
  text "14" at 2817.84,258.35 h60
  text "0.200mm (7.87mil)" at 3150,258.35 h60
  text "PTH" at 3786.48,258.35 h60
  text "Round" at 4045.68,258.35 h60
  text "Top Layer - Bottom Layer" at 4420.92,258.35 h60
  text "107" at 2817.84,133.85 h60
  text "0.305mm (12.00mil)" at 3150,133.85 h60
  text "PTH" at 3786.48,133.85 h60
  text "Round" at 4045.68,133.85 h60
  text "Top Layer - Bottom Layer" at 4420.92,133.85 h60
  text "3" at 2817.84,9.35 h60
  text "1.016mm (40.00mil)" at 3150,9.35 h60
  text "PTH" at 3786.48,9.35 h60
  text "Round" at 4045.68,9.35 h60
  text "Top Layer - Bottom Layer" at 4420.92,9.35 h60
  text "3" at 2817.84,-115.15 h60
  text "1.050mm (41.34mil)" at 3150,-115.15 h60
  text "PTH" at 3786.48,-115.15 h60
  text "Round" at 4045.68,-115.15 h60
  text "Top Layer - Bottom Layer" at 4420.92,-115.15 h60
  text "12" at 2817.84,-239.65 h60
  text "1.100mm (43.31mil)" at 3150,-239.65 h60
  text "PTH" at 3786.48,-239.65 h60
  text "Round" at 4045.68,-239.65 h60
  text "Top Layer - Bottom Layer" at 4420.92,-239.65 h60
  text "2" at 2817.84,-364.15 h60
  text "1.150mm (45.28mil)" at 3150,-364.15 h60
  text "PTH" at 3786.48,-364.15 h60
  text "Round" at 4045.68,-364.15 h60
  text "Top Layer - Bottom Layer" at 4420.92,-364.15 h60
  text "6" at 2817.84,-488.65 h60
  text "1.300mm (51.18mil)" at 3150,-488.65 h60
  text "PTH" at 3786.48,-488.65 h60
  text "Round" at 4045.68,-488.65 h60
  text "Top Layer - Bottom Layer" at 4420.92,-488.65 h60
  text "2" at 2817.84,-613.15 h60
  text "1.350mm (53.15mil)" at 3150,-613.15 h60
  text "PTH" at 3786.48,-613.15 h60
  text "Round" at 4045.68,-613.15 h60
  text "Top Layer - Bottom Layer" at 4420.92,-613.15 h60
  text "2" at 2817.84,-737.65 h60
  text "1.651mm (65.00mil)" at 3150,-737.65 h60
  text "NPTH" at 3786.48,-737.65 h60
  text "Rectangle" at 4045.68,-737.65 h60
  text "Top Layer - Bottom Layer" at 4420.92,-737.65 h60
  text "151 Total" at 2817.84,-862.15 h60
  text "Slot definitions :" at 2517.18,-949.3 h60
  text "Routed Path Length" at 2967.83,-949.3 h60
  text "= Calculated from tool start centre position to tool end centre position." at 3507.68,-949.3 h60
  text "Hole Length" at 2967.83,-999.1 h60
  text "= Routed Path Length + Tool Size = Slot length as defined in the PCB layout" at 3307.83,-999.1 h60
  text "FOR 7.87MIL DRILL +0/-7.87MIL" at 2472,-1136 h60
  text "FOR 12MIL DRILL +0/-12MIL" at 2472,-1250 h60
  text "FOR PTH DRILL +/-3MIL" at 2472,-1356 h60
  text "FOR NPTH DRILL +/-2MIL" at 2473,-1476 h60
  text ".Layer_Name" at -1723,-2858.49 h60
M17 Embedded Cavity:
  text ".Layer_Name" at -1723,-2858.49 h60
M18 Embedded Assembly:
  text ".Layer_Name" at -1723,-2858.49 h60
M19 Embedded Keepout:
  text ".Layer_Name" at -1723,-2858.49 h60

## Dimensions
-2300,-2400 to -1300,-2400 on M2 Board Dimensions
-1279.53,0 to 1279.53,0 on M2 Board Dimensions
0,0 to 1179.21,1179.21 on M2 Board Dimensions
